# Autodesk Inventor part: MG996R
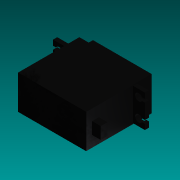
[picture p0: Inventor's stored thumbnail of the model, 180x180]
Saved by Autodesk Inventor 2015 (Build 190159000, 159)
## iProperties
Created: 2016-02
Part Number: MG996R
Material: Generic
Document SubType Name: Modeling
Designer: Rafał
Density: 1 g/cm^3
Appearance: Smooth - Black
Author: Rafał
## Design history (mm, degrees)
sketch "Sketch1"
  geometry: L1 (0, 0)-(40, 0); L2 (40, 0)-(40, 27.5); L3 (40, 27.5)-(47, 27.5); L4 (47, 27.5)-(47, 30); L5 (47, 30)-(40, 30); L6 (40, 30)-(40, 38.5); L7 (40, 38.5)-(5.5, 38.5); L8 (5.5, 38.5)-(5.5, 36); L9 (5.5, 36)-(0, 36); L10 (0, 36)-(0, 30); L11 (0, 30)-(-7, 30); L12 (-7, 30)-(-7, 27.5); L13 (-7, 27.5)-(0, 27.5); L14 (0, 27.5)-(0, 0)
  constraints: 28 end point, 8 perpendicular, 7 point on line, 2 vertical, 1 horizontal
  dimensions: "d0" = 40 distance of L1.start L1.end; "d1" = 27.5 distance of L1.end L2.end; "d2" = 7 distance of L2.end L3.end; "d3" = 2.5 distance of L3.end L4.end; "d4" = 8.5 distance of L5.end L6.end; "d5" = 34.5 distance of L6.end L7.end; "d6" = 2.5 distance of L7.end L8.end; "d7" = 7 distance of L10.end L11.end
extrude "Extrusion1" new body sketch "Sketch1" distance "d8" = 20; taper "d9" = 0 deg
sketch "Sketch2"
  geometry: L1 (7, 0)-(0, 0) reference; L2 (0, 0)-(0, -20) reference; L3 (0, 0)-(0, -20) reference; L4 (3.6, -4.6)-(0, -4.6); L5 (0, -4.6)-(0, -3.6); L6 (0, -3.6)-(3.6, -3.6); L7 (3.6, -3.6)-(3.6, -4.6); L8 (3.6, -4.6)-(0, -4.6); L9 (0, -4.6)-(0, -5.6); L10 (0, -5.6)-(3.6, -5.6); L11 (3.6, -5.6)-(3.6, -4.6); L12 (0, -10)-(54, -10); L13 (54, 0)-(54, -20) reference; L14 (27, -10)-(27, -2.45); L15 (7, 0)-(7, -20) reference; L16 (0, 0)-(7, 0); L17 (7, 0)-(7, -0.5); L18 (7, -0.5)-(0, -0.5); L19 (0, -0.5)-(0, 0); L20 (0, -14.4)-(3.6, -14.4); L21 (3.6, -14.4)-(3.6, -15.4); L22 (3.6, -16.4)-(3.6, -15.4); L23 (0, -16.4)-(3.6, -16.4); L24 (0, -15.4)-(0, -16.4); L25 (0, -15.4)-(0, -14.4); L26 (3.6, -15.4)-(0, -15.4); L27 (7, -20)-(0, -20); L28 (7, -19.5)-(0, -19.5); L29 (7, -20)-(7, -19.5); L30 (7, -20)-(7, 0); L31 (0, -19.5)-(0, -20); L32 (7, 0)-(7, -0.5); L33 (7, -19.5)-(7, -20); L34 (50.4, -14.4)-(50.4, -15.4); L35 (50.4, -16.4)-(50.4, -15.4); L36 (54, -14.4)-(50.4, -14.4); L37 (50.4, -15.4)-(54, -15.4); L38 (54, -15.4)-(54, -14.4); L39 (54, -16.4)-(50.4, -16.4); L40 (54, -15.4)-(54, -16.4); L41 (54, -19.5)-(54, -20); L42 (47, -19.5)-(54, -19.5); L43 (47, -20)-(54, -20); L44 (47, 0)-(54, 0); L45 (54, 0)-(54, -20); L46 (54, 0)-(54, -20); L47 (47, 0)-(47, -20); L48 (47, -20)-(47, 0); L49 (47, -19.5)-(47, -20); L50 (47, -20)-(47, -19.5); L51 (50.4, -4.6)-(54, -4.6); L52 (54, -4.6)-(54, -3.6); L53 (54, -3.6)-(50.4, -3.6); L54 (50.4, -3.6)-(50.4, -4.6); L55 (54, -5.6)-(50.4, -5.6); L56 (50.4, -4.6)-(54, -4.6); L57 (54, -4.6)-(54, -5.6); L58 (50.4, -5.6)-(50.4, -4.6); L59 (47, -0.5)-(54, -0.5); L60 (54, 0)-(47, 0); L61 (47, 0)-(47, -0.5); L62 (47, 0)-(47, -0.5); L63 (54, -0.5)-(54, 0); L64 (3.6, -16.4)-(0, -16.4)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; C1 r 2.15 at (3.6, -4.6); C2 r 2.15 at (3.6, -15.4); C3 r 2.15 at (50.4, -15.4); C4 r 2.15 at (50.4, -4.6)
  constraints: 132 end point, 36 symmetric about line, 10 parallel, 8 point on line, 5 horizontal, 5 perpendicular, 4 centre point, 3 midpoint, 3 vertical, 3 other
  dimensions: "d10" = 4.3 diameter of C1; "d11" = 4.6 distance from line of L1 L4.start; "d12" = 3.6 distance from line of L2 L4.start; "d13" = 1 distance of L4.end L5.end; "d14" = 1 distance of L9.end L8.end; "d15" = 0.5 distance of L16.end L17.end
extrude "Extrusion2" cut sketch "Sketch2" distance "d16" = 20; taper "d17" = 0 deg
sketch "Sketch3"
  geometry: 1 further point
sketch "Sketch4"
  geometry: L1 (34.5, -20)-(0, -20) reference; L2 (34.5, 0)-(34.5, -20) reference; C1 r 6.65 at (25, -10); 1 further point
  constraints: 1 centre point
  dimensions: "d18" = 13.3 diameter of C1; "d19" = 10 distance from line of L1 C1.centre; "d20" = 9.5 distance from line of L2 C1.centre
extrude "Extrusion3" join sketch "Sketch4" distance "d21" = 2; taper "d22" = 0 deg
sketch "Sketch5"
  geometry: C1 r 6.65 at (0, 0) reference; C2 r 3 at (0, 0); 1 further point
  constraints: 1 centre point, 1 coincident
  dimensions: "d23" = 6 diameter of C2
extrude "Extrusion4" join sketch "Sketch5" distance "d24" = 4; taper "d25" = 0 deg
sketch "Sketch6"
  geometry: L1 (6.5, 7.5)-(13.5, 7.5); L2 (13.5, 7.5)-(13.5, 3.5); L3 (13.5, 3.5)-(6.5, 3.5); L4 (6.5, 3.5)-(6.5, 7.5); L5 (20, 0)-(0, 0) reference; L6 (0, 0)-(0, 38.5) reference
  constraints: 8 end point, 2 parallel, 1 horizontal, 1 perpendicular
  dimensions: "d26" = 7 distance of L2.end L3.end; "d27" = 4 distance of L1.end L2.end; "d28" = 3.5 distance between parallel lines of L5 L3; "d29" = 6.5 distance between parallel lines of L6 L4
extrude "Extrusion5" join sketch "Sketch6" distance "d30" = 5; taper "d31" = 0 deg
body "Solid1"
